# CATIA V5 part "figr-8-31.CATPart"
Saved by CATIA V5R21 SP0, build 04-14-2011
Part number: Part1
Bounding box of the stored display mesh (mm): x -50 to 50, y -75 to 125, z 0 to 40
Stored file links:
  D:\CATIA V5R21 E-RESOURCES\CATIA-V5R21\catia-v5r21-prt\c08-catia-v5r20-prt\c08-catia-v5r21-figr-8-31.CATPart
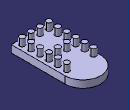
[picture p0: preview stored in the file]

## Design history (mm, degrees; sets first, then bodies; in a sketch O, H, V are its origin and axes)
Body1 (main body)
  Sketch1 on xy-plane, origin (0, 0, 0), H (1, 0, 0), V (0, 1, 0)
    line L1 (50, 75) -> (50, -75)
    line L2 (50, -75) -> (-50, -75)
    line L3 (-50, -75) -> (-50, 75)
    arc A1 centre (0, 75) radius 50 from (-50, 75) to (50, 75) cw
    point P5 (0, 75)
    axis line L4 (50, -75) -> (-50, 75)
    length L2 = 100
    distance P5 L2 = 150
    horizontal: L2 H
    vertical: L1 V, L3 V
    tangency: A1 L3, A1 L1
    midpoint: O L4
  Pad1: profile Sketch1, direction (0, 0, 1), length 20
  Sketch2 on face of Pad1, origin (0, 0, 20), H (1, 0, 0), V (0, 1, 0)
    circle A1 centre (35, -60) radius 7.5
    point P1 (35, -60)
    reference projected line E1 (-50, -75) -> (50, -75) from edge [face of Pad1 | face of Pad1]
    reference projected line E2 (50, -75) -> (50, 75) from edge [face of Pad1 | face of Pad1]
    distance P1 E1 = 15
    distance P1 E2 = 15
    radius A1 = 7.5
  Pad2: profile Sketch2, direction (0, 0, 1), length 20
  RectPattern1: of Pad2, direction 1 instances 4, spacing 25, along edge [face of Pad1 | face of Pad1] reversed, direction 2 instances 6, spacing 25, along edge [face of Pad1 | face of Pad1]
